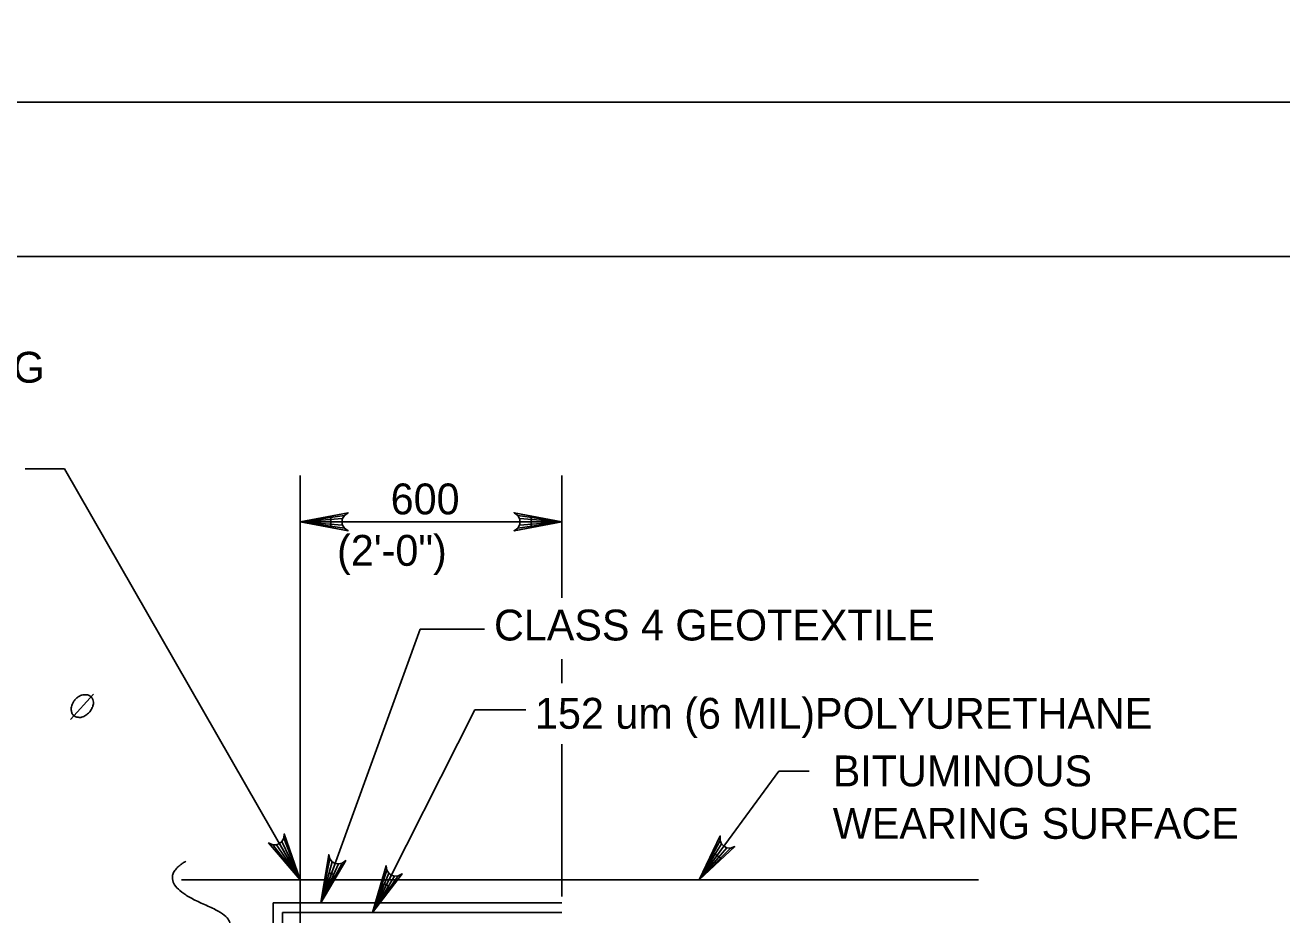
# Model space of a CAD drawing. Extents: x 638263 to 640360, y 293683 to 298655.
# Drawn here: x 639617.3 to 639739.4, y 297762.5 to 297849 of the extents above; entities that cross this region are included whole.
import ezdxf

# ---------------------------------------------------------------- set-up
doc = ezdxf.new("R2010")
doc.units = 0
for name, color, linetype in [('2', 7, 'Continuous'), ('3', 7, 'Continuous'), ('4', 7, 'Continuous'), ('5', 7, 'Continuous'), ('PLT-BNDY', 7, 'Continuous')]:
    doc.layers.add(name, color=color, linetype=linetype)

msp = doc.modelspace()

# ---------------------------------------------------------------- linework, layer by layer
at = {"layer": '2'}
msp.add_line((639316.46, 297826.46), (640102.46, 297826.46), dxfattribs=at)
at = {"layer": '3'}
for p, q in [((639644.03, 297764.25), (639644.03, 297805.18)), ((639669.47, 297793.29), (639669.47, 297805.18)), ((639644.03, 297800.68), (639669.47, 297800.68)), ((639655.7, 297790.25), (639661.96, 297790.25)), ((639669.47, 297785), (639669.47, 297787.32)), ((639661.01, 297782.41), (639665.96, 297782.41)), ((639669.47, 297764.25), (639669.47, 297779.06)), ((639682.79, 297765.87), (639690.55, 297776.44)), ((639690.55, 297776.44), (639693.5, 297776.44))]:
    msp.add_line(p, q, dxfattribs=at)
for points in [[(639644.03, 297800.68), (639648.69, 297801.55), (639648.33, 297801.3), (639648.14, 297800.99), (639648.09, 297800.68), (639648.14, 297800.36), (639648.33, 297800.05), (639648.69, 297799.8), (639644.03, 297800.68), (639648.33, 297800.05), (639648.14, 297800.36), (639644.03, 297800.68), (639648.09, 297800.68), (639648.14, 297800.99), (639644.03, 297800.68), (639648.33, 297801.3)], [(639669.47, 297800.68), (639664.81, 297799.8), (639665.17, 297800.05), (639665.36, 297800.36), (639665.41, 297800.68), (639665.36, 297800.99), (639665.17, 297801.3), (639664.81, 297801.55), (639669.47, 297800.68), (639665.17, 297801.3), (639665.36, 297800.99), (639669.47, 297800.68), (639665.41, 297800.68), (639665.36, 297800.36), (639669.47, 297800.68), (639665.17, 297800.05)], [(639646.05, 297763.65), (639655.7, 297790.25)], [(639651.06, 297762.69), (639661.01, 297782.41)], [(639682.79, 297765.87), (639684.84, 297770.14), (639684.83, 297769.7), (639684.98, 297769.37), (639685.19, 297769.14), (639685.48, 297769), (639685.84, 297768.96), (639686.25, 297769.11), (639682.79, 297765.87), (639685.84, 297768.96), (639685.48, 297769), (639682.79, 297765.87), (639685.19, 297769.14), (639684.98, 297769.37), (639682.79, 297765.87), (639684.83, 297769.7)], [(639646.05, 297763.65), (639646.82, 297768.33), (639646.93, 297767.91), (639647.16, 297767.63), (639647.44, 297767.47), (639647.75, 297767.42), (639648.11, 297767.49), (639648.46, 297767.74), (639646.05, 297763.65), (639648.11, 297767.49), (639647.75, 297767.42), (639646.05, 297763.65), (639647.44, 297767.47), (639647.16, 297767.63), (639646.05, 297763.65), (639646.93, 297767.91)], [(639651.06, 297762.69), (639652.38, 297767.24), (639652.44, 297766.81), (639652.64, 297766.51), (639652.89, 297766.32), (639653.19, 297766.22), (639653.56, 297766.25), (639653.94, 297766.46), (639651.06, 297762.69), (639653.56, 297766.25), (639653.19, 297766.22), (639651.06, 297762.69), (639652.89, 297766.32), (639652.64, 297766.51), (639651.06, 297762.69), (639652.44, 297766.81)]]:
    msp.add_lwpolyline(points, dxfattribs=at)
for points in [[(639647.03, 297801.18), (639647.03, 297800.18), (639644.03, 297800.68)], [(639666.47, 297801.18), (639666.47, 297800.18), (639669.47, 297800.68)], [(639684.93, 297767.96), (639684.14, 297768.54), (639682.79, 297765.87)], [(639646.05, 297763.65), (639647.31, 297766.39), (639646.84, 297766.56)], [(639651.06, 297762.69), (639652.64, 297765.26), (639652.19, 297765.48)]]:
    msp.add_lwpolyline(points, close=True, dxfattribs=at)
at = {"layer": '4'}
msp.add_line((639621.72, 297781.46), (639623.96, 297783.91), dxfattribs=at)
msp.add_spline([(639623.73, 297783.67), (639623.55, 297783.8), (639623.37, 297783.85), (639623.16, 297783.87), (639623.03, 297783.87), (639622.81, 297783.82), (639622.61, 297783.73), (639622.48, 297783.65), (639622.21, 297783.44), (639622.01, 297783.17), (639621.88, 297782.92), (639621.81, 297782.69), (639621.79, 297782.47), (639621.81, 297782.29), (639621.9, 297782.02), (639622, 297781.89), (639622.19, 297781.74), (639622.48, 297781.67), (639622.81, 297781.68), (639623.23, 297781.87), (639623.53, 297782.14), (639623.76, 297782.45), (639623.91, 297782.79), (639623.96, 297783.15), (639623.89, 297783.39), (639623.74, 297783.67)], degree=3, dxfattribs=at)
at = {"layer": '5'}
for p, q in [((639621.14, 297805.81), (639617.32, 297805.81)), ((639644.05, 297765.87), (639621.14, 297805.81)), ((639632.51, 297765.87), (639709.93, 297765.87)), ((639644.03, 297765.87), (639644.03, 297667.88)), ((639641.41, 297763.65), (639669.47, 297763.65)), ((639641.41, 297763.65), (639641.41, 297665.26)), ((639642.33, 297762.69), (639669.47, 297762.69)), ((639642.33, 297762.69), (639642.33, 297666.25))]:
    msp.add_line(p, q, dxfattribs=at)
msp.add_lwpolyline([(639644.05, 297765.87), (639640.97, 297769.47), (639641.37, 297769.29), (639641.73, 297769.28), (639642.03, 297769.39), (639642.27, 297769.59), (639642.45, 297769.91), (639642.49, 297770.34), (639644.05, 297765.87), (639642.45, 297769.91), (639642.27, 297769.59), (639644.05, 297765.87), (639642.03, 297769.39), (639641.73, 297769.28), (639644.05, 297765.87), (639641.37, 297769.29)], dxfattribs=at)
msp.add_open_spline([(639632.93, 297767.68), (639629.56, 297765.66), (639640.11, 297761.2), (639633.58, 297760.06)], degree=2, dxfattribs=at)
at = {"layer": 'PLT-BNDY'}
for points in [[(639276.46, 298435.46), (640117.46, 298435.46), (640117.46, 297841.46), (639276.46, 297841.46)], [(639276.46, 297841.46), (640117.46, 297841.46), (640117.46, 297247.46), (639276.46, 297247.46)]]:
    msp.add_lwpolyline(points, close=True, dxfattribs=at)

# ---------------------------------------------------------------- texts
at = {"layer": '3'}
for s, p in [('SAW CUT BITUMINOUS WEARING', (639554.15, 297814.2)), ('600', (639652.83, 297801.4)), ('(2\'-0")', (639647.62, 297796.4)), ('CLASS 4 GEOTEXTILE', (639662.87, 297789.14)), ('152 um (6 MIL)POLYURETHANE', (639666.85, 297780.56)), ('BITUMINOUS', (639695.78, 297774.96)), ('WEARING SURFACE', (639695.78, 297769.86))]:
    msp.add_text(s, height=3, dxfattribs=at).set_placement(p)

doc.saveas('drawing.dxf')
